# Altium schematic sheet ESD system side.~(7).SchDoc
size A3; SheetNumber: 14; SheetTotal: 15
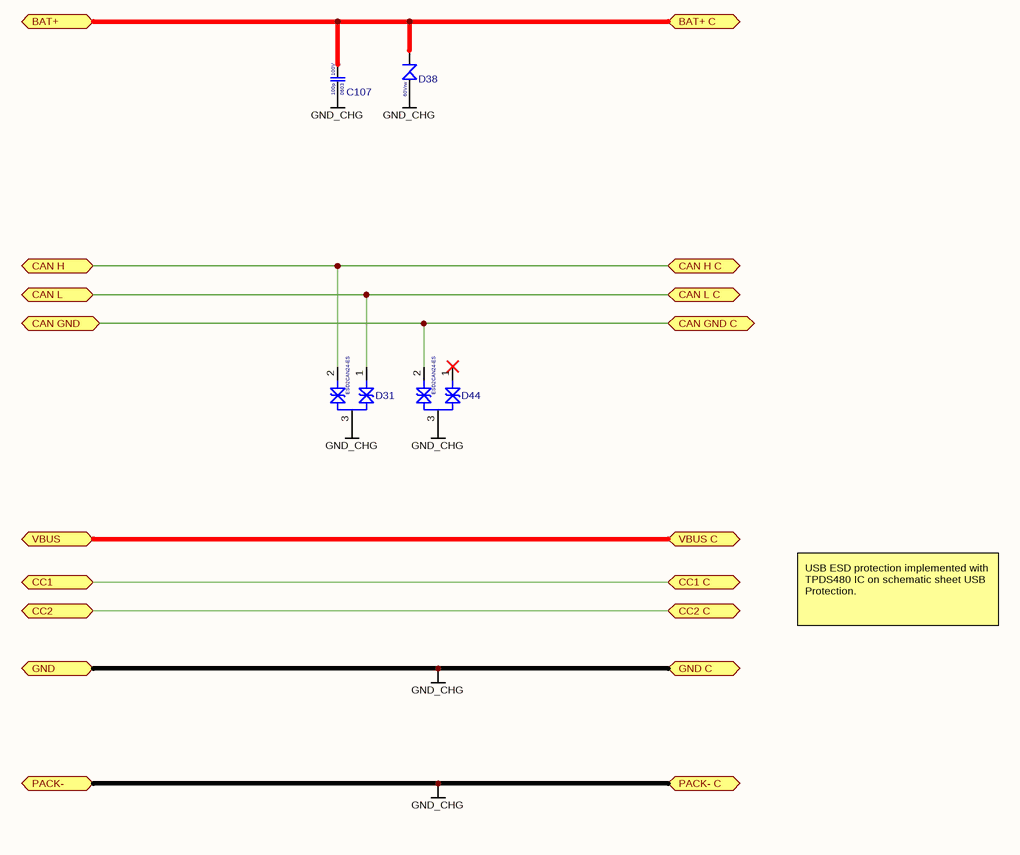
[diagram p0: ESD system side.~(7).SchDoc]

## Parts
C107  Voltage Rating: 100V  Case Code (Imperial): 0603  Capacitance: 100p  [CAP 0603]  (hidden comment: CC0603JRNPO0BN101)
D31  ESD2CAN24-ES  [SOT-23 123]
D38  Reverse Voltage: 60Vrw  [DO-214AA]  (hidden comment: SMBJ60A)
D44  ESD2CAN24-ES  [SOT-23 123]

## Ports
BAT+ (bidir, see Arhitecture[6A], BAT+ to 5V1 STEP-DOWN[3B], BMS[1A], BQ34Z100 FUEL GAUGE[3A], BQ76952 BMS[1A], ESD battery side[5A]), BAT+ C (bidir, see Arhitecture[7A]), CAN GND (bidir, see Arhitecture[6B], BMS[8B], MCU[8B]), CAN GND C (bidir, see Arhitecture[7B]), CAN H (bidir, see Arhitecture[6B], BMS[8B], MCU[8A]), CAN H C (bidir, see Arhitecture[7B]), CAN L (bidir, see Arhitecture[6B], BMS[8B], MCU[8B]), CAN L C (bidir, see Arhitecture[7B]), CC1 (bidir, see Arhitecture[6B], CHARGER[8C]), CC1 C (bidir, see Arhitecture[7B]), CC2 (bidir, see Arhitecture[6C], CHARGER[8C]), CC2 C (bidir, see Arhitecture[7C]), GND (bidir, see Arhitecture[6C], CHARGER[8C]), GND C (bidir, see Arhitecture[7C]), PACK- (bidir, see Arhitecture[6D], BMS[8D], CHARGER[1C]), PACK- C (bidir, see Arhitecture[7D]), VBUS (bidir, see Arhitecture[6B], CHARGER[8C]), VBUS C (bidir, see Arhitecture[7B])

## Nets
GND_CHG: C107.1 D31.3 D38.A D44.3 ; port GND C, port GND, port PACK- C, port PACK-
BAT+: C107.2 D38.K ; port BAT+ C, port BAT+
CAN GND: D44.2 ; port CAN GND, port CAN GND C
CAN H: D31.2 ; port CAN H, port CAN H C
CAN L: D31.1 ; port CAN L, port CAN L C
CC1: port CC1 C, port CC1
CC2: port CC2 C, port CC2
VBUS: port VBUS C, port VBUS

Not connected (* = marked no-connect by the designer): D44 1*

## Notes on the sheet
- USB ESD protection implemented with TPDS480 IC on schematic sheet USB Protection.

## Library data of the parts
C107 = CC0603JRNPO0BN101: Cap 100pF 100V 0603 NP0; Manufacturer: Yageo; Manufacturer Part Number: CC0603KRX7R9BB104
D31 D44 = ESD2CAN24-ES: ESD TVS CAN; Manufacturer: ElecSuper
D38 = SMBJ60A: TVS ESD Zener UniD 60Vrw 1uA; Manufacturer: Shandong Jingdao Microelectronics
